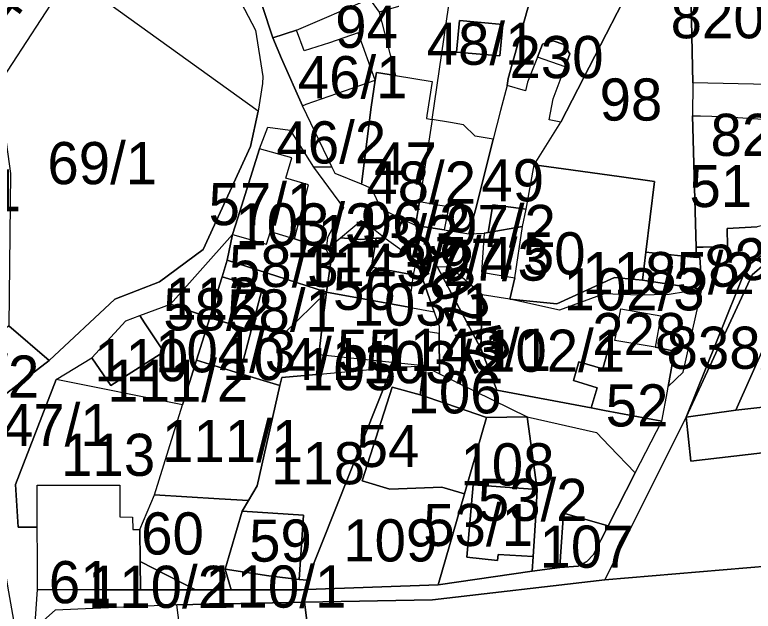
# Model space of a CAD drawing. Extents: x -623250 to -619626, y -1079612 to -1075424.
# Drawn here: x -621422.3 to -621247.2, y -1077337.8 to -1077196.3 of the extents above; entities that cross this region are included whole.
import ezdxf

# ---------------------------------------------------------------- set-up
doc = ezdxf.new("R2010")
doc.units = 0
doc.layers.add('Parcela nároku', color=7, linetype='Continuous')
doc.layers.add('Parcelní číslo', color=7, linetype='Continuous')

msp = doc.modelspace()

# ---------------------------------------------------------------- linework, layer by layer
at = {"layer": 'Parcela nároku'}
for points in [[(-621283.01, -1077121.21), (-621280.89, -1077123.84), (-621305.26, -1077211.45), (-621305.57, -1077213.07), (-621307.14, -1077219), (-621308.84, -1077225.83), (-621313.14, -1077225.09), (-621315.88, -1077222.42), (-621319, -1077221.89), (-621323.33, -1077221.15), (-621310.49, -1077133.23)], [(-621280.89, -1077123.84), (-621275.26, -1077129.83), (-621268.72, -1077174.87), (-621292.8, -1077221.78), (-621295.55, -1077221.25), (-621294.6, -1077216.21), (-621291.75, -1077208.69), (-621290.65, -1077205.56), (-621292.09, -1077203.39), (-621294.65, -1077202.49), (-621297.14, -1077203.31), (-621298.37, -1077206.39), (-621300.69, -1077212.33), (-621301.16, -1077214.33), (-621305.57, -1077213.07), (-621305.26, -1077211.45)], [(-621323.3, -1077212.12), (-621324.59, -1077220.22), (-621324.7, -1077220.92), (-621323.33, -1077221.15), (-621310.49, -1077133.23), (-621335.24, -1077144.05), (-621330.77, -1077177.42), (-621328.62, -1077193.52), (-621335.86, -1077195.7), (-621332.02, -1077210.68)], [(-621344.27, -1077183.78), (-621362.96, -1077165.79), (-621384.05, -1077157.04), (-621368.64, -1077178.95), (-621361.11, -1077201.81), (-621355.51, -1077199.95), (-621338.15, -1077192.45), (-621342.75, -1077185.94)], [(-621409.34, -1077186.93), (-621385.94, -1077160.33), (-621365.2, -1077199.94), (-621363.51, -1077210.97), (-621363.55, -1077212.6), (-621364.55, -1077219.18)], [(-621234.38, -1077170.7), (-621225.78, -1077225.43), (-621243.53, -1077212.83), (-621261.46, -1077212.45), (-621262.25, -1077175.25)], [(-621261.54, -1077220.29), (-621260.68, -1077251.44), (-621260.63, -1077253.88), (-621272.64, -1077252.66), (-621270.59, -1077235.87), (-621278.94, -1077234.7), (-621292.18, -1077232.85), (-621299.13, -1077231.88), (-621292.8, -1077221.78), (-621268.72, -1077174.87), (-621262.25, -1077175.25), (-621261.46, -1077212.45)], [(-621414.18, -1077278.35), (-621398.59, -1077263.79), (-621387.96, -1077259.7), (-621377.6, -1077252.01), (-621366.43, -1077227.54), (-621364.55, -1077219.18), (-621409.34, -1077186.93), (-621429.78, -1077218.32), (-621424.96, -1077221.94), (-621423.29, -1077233.96), (-621423.71, -1077270.11)], [(-621335.86, -1077195.7), (-621332.02, -1077210.68), (-621336.56, -1077210.03), (-621336.84, -1077211.83), (-621340.84, -1077200.6), (-621347.63, -1077202.95), (-621353.64, -1077204.86), (-621355.51, -1077199.95), (-621338.15, -1077192.45)], [(-621316.87, -1077197.68), (-621306.56, -1077198.59), (-621307.27, -1077206.06), (-621317.58, -1077205.15)], [(-621317.58, -1077205.15), (-621307.27, -1077206.06), (-621306.56, -1077198.59), (-621316.87, -1077197.68)], [(-621353.64, -1077204.86), (-621355.51, -1077199.95), (-621361.11, -1077201.81), (-621359.04, -1077206.69), (-621354.1, -1077217.94), (-621353.17, -1077217.54), (-621336.84, -1077211.83), (-621340.84, -1077200.6), (-621347.63, -1077202.95)], [(-621294.65, -1077202.49), (-621292.09, -1077203.39), (-621290.65, -1077205.56), (-621291.75, -1077208.69), (-621298.37, -1077206.39), (-621297.14, -1077203.31)], [(-621307.14, -1077219), (-621308.84, -1077225.83), (-621312.88, -1077242.04), (-621314.62, -1077248.24), (-621310.96, -1077248.15), (-621310.04, -1077247.99), (-621308.92, -1077241.39), (-621301.01, -1077242.43), (-621299.13, -1077231.88), (-621292.8, -1077221.78), (-621295.55, -1077221.25), (-621294.6, -1077216.21), (-621291.75, -1077208.69), (-621298.37, -1077206.39), (-621300.69, -1077212.33), (-621301.16, -1077214.33), (-621305.57, -1077213.07)], [(-621332.02, -1077210.68), (-621323.3, -1077212.12), (-621324.59, -1077220.22), (-621324.7, -1077220.92), (-621323.33, -1077221.15), (-621326.33, -1077240.57), (-621327.29, -1077246.34), (-621335.32, -1077242.42), (-621337.74, -1077237.5), (-621340.1, -1077236.53), (-621337.82, -1077218.19), (-621336.84, -1077211.83), (-621336.56, -1077210.03)], [(-621353.17, -1077217.54), (-621336.84, -1077211.83), (-621337.82, -1077218.19), (-621340.1, -1077236.53), (-621346.34, -1077233.96), (-621347.1, -1077232.4), (-621354.1, -1077217.94)], [(-621261.46, -1077212.45), (-621261.54, -1077220.29), (-621259.67, -1077220.32), (-621254.27, -1077220.41), (-621241.4, -1077221.33), (-621240.16, -1077230.42), (-621236.21, -1077229.88), (-621224.13, -1077237), (-621225.78, -1077225.43), (-621243.53, -1077212.83)], [(-621254.27, -1077220.41), (-621241.4, -1077221.33), (-621240.16, -1077230.42), (-621236.21, -1077229.88), (-621234.49, -1077242.48), (-621234.26, -1077244.2), (-621243.25, -1077245.92), (-621246.23, -1077246.61), (-621253.36, -1077246.98), (-621253.24, -1077251.28), (-621259.06, -1077251.41), (-621260.68, -1077251.44), (-621261.54, -1077220.29), (-621259.67, -1077220.32)], [(-621319.38, -1077241.83), (-621320.51, -1077247.34), (-621314.62, -1077248.24), (-621312.88, -1077242.04), (-621308.84, -1077225.83), (-621313.14, -1077225.09), (-621315.88, -1077222.42), (-621319, -1077221.89), (-621323.33, -1077221.15), (-621326.33, -1077240.57), (-621321.51, -1077241.51)], [(-621362.28, -1077222.94), (-621357, -1077223.71), (-621351.46, -1077232.43), (-621344.34, -1077242.13), (-621348.18, -1077249.16), (-621348.48, -1077252.01), (-621355.98, -1077249.43), (-621352.62, -1077236.67), (-621357.99, -1077235.06), (-621356.6, -1077230.27), (-621364.27, -1077228.08)], [(-621364.27, -1077228.08), (-621369.38, -1077244.49), (-621370.67, -1077248.45), (-621362.58, -1077250.74), (-621361.69, -1077247.69), (-621355.98, -1077249.43), (-621352.62, -1077236.67), (-621357.99, -1077235.06), (-621356.6, -1077230.27)], [(-621282.44, -1077290.17), (-621285.64, -1077289.56), (-621307.96, -1077285.34), (-621311.76, -1077275.51), (-621322.05, -1077256.19), (-621327.29, -1077246.34), (-621335.32, -1077242.42), (-621337.74, -1077237.5), (-621340.1, -1077236.53), (-621346.34, -1077233.96), (-621347.1, -1077232.4), (-621351.46, -1077232.43), (-621344.34, -1077242.13), (-621348.18, -1077249.16), (-621348.48, -1077252.01), (-621345.09, -1077249.2), (-621340.12, -1077245.09), (-621336.85, -1077247.39), (-621334.48, -1077249.33), (-621327.12, -1077254.63), (-621322.86, -1077266.78), (-621321.66, -1077270.19), (-621321.65, -1077271.91), (-621321.59, -1077281.47), (-621300.81, -1077291.72), (-621284.31, -1077295.45), (-621281.27, -1077298.62), (-621275.15, -1077305.01), (-621268.83, -1077292.74)], [(-621299.13, -1077231.88), (-621292.18, -1077232.85), (-621278.94, -1077234.7), (-621270.59, -1077235.87), (-621272.64, -1077252.66), (-621273.45, -1077259.28), (-621280.07, -1077258.66), (-621293.78, -1077264.9), (-621304.89, -1077263.8), (-621303.75, -1077258.75), (-621301.93, -1077246.55), (-621301.01, -1077242.43)], [(-621327.29, -1077246.34), (-621326.33, -1077240.57), (-621321.51, -1077241.51), (-621319.38, -1077241.83), (-621320.51, -1077247.34)], [(-621308.92, -1077241.39), (-621310.04, -1077247.99), (-621301.93, -1077246.55), (-621301.01, -1077242.43)], [(-621345.09, -1077249.2), (-621340.12, -1077245.09), (-621336.85, -1077247.39), (-621334.48, -1077249.33), (-621336.6, -1077249.29), (-621340.33, -1077249.63)], [(-621311.6, -1077257.38), (-621303.75, -1077258.75), (-621304.89, -1077263.8), (-621311.44, -1077262.76), (-621319.09, -1077256.09), (-621322.05, -1077256.19), (-621327.29, -1077246.34), (-621320.51, -1077247.34), (-621314.62, -1077248.24), (-621310.96, -1077248.15)], [(-621310.96, -1077248.15), (-621311.6, -1077257.38), (-621303.75, -1077258.75), (-621301.93, -1077246.55), (-621310.04, -1077247.99)], [(-621385.38, -1077264.96), (-621370.67, -1077248.45), (-621371.95, -1077254.49), (-621373.14, -1077258.45), (-621373.74, -1077260.43), (-621376.08, -1077268.19)], [(-621371.95, -1077254.49), (-621370.67, -1077248.45), (-621362.58, -1077250.74), (-621361.69, -1077247.69), (-621355.98, -1077249.43), (-621348.48, -1077252.01), (-621347.24, -1077254.38), (-621348.39, -1077262.15)], [(-621348.48, -1077252.01), (-621345.09, -1077249.2), (-621340.33, -1077249.63), (-621336.6, -1077249.29), (-621337.72, -1077256.19), (-621327.8, -1077257.99), (-621328.83, -1077265.7), (-621348.39, -1077262.15), (-621347.24, -1077254.38)], [(-621337.72, -1077256.19), (-621336.6, -1077249.29), (-621334.48, -1077249.33), (-621327.12, -1077254.63), (-621327.8, -1077257.99)], [(-621248.65, -1077256), (-621241.85, -1077250.96), (-621233.44, -1077250.14), (-621234.48, -1077252.35), (-621238.42, -1077252.8), (-621242.78, -1077254.01), (-621247.45, -1077257.99), (-621263.08, -1077291.76)], [(-621214.67, -1077268.16), (-621211.16, -1077267.99), (-621209.97, -1077285.55), (-621251.27, -1077290.14), (-621234.48, -1077252.35), (-621212.23, -1077250.58), (-621211.9, -1077255.8), (-621215.39, -1077255.93), (-621220.22, -1077256.12), (-621228.03, -1077256.42), (-621227.94, -1077259.11), (-621228.58, -1077259.16), (-621228.11, -1077268.82), (-621219.54, -1077268.4)], [(-621260.63, -1077253.88), (-621259.84, -1077253.85), (-621259.33, -1077261.42), (-621273.45, -1077259.28), (-621272.64, -1077252.66)], [(-621242.78, -1077254.01), (-621238.42, -1077252.8), (-621234.48, -1077252.35), (-621251.27, -1077290.14), (-621263.08, -1077291.76), (-621247.45, -1077257.99)], [(-621371.95, -1077254.49), (-621348.39, -1077262.15), (-621358.41, -1077271.96), (-621365.87, -1077269.81), (-621363.64, -1077261.33), (-621373.14, -1077258.45)], [(-621327.8, -1077257.99), (-621328.83, -1077265.7), (-621322.86, -1077266.78), (-621327.12, -1077254.63)], [(-621319.09, -1077256.09), (-621322.05, -1077256.19), (-621311.76, -1077275.51), (-621311.44, -1077262.76)], [(-621373.14, -1077258.45), (-621363.64, -1077261.33), (-621365.87, -1077269.81), (-621366.23, -1077271.2), (-621370.99, -1077269.68), (-621376.08, -1077268.19), (-621373.74, -1077260.43)], [(-621280.07, -1077258.66), (-621273.45, -1077259.28), (-621259.33, -1077261.42), (-621267.12, -1077262.69), (-621274.19, -1077262.86), (-621282.52, -1077262.55), (-621293.15, -1077266.4), (-621304.89, -1077263.8), (-621293.78, -1077264.9)], [(-621358.41, -1077271.96), (-621348.39, -1077262.15), (-621349.23, -1077268.87), (-621350.23, -1077276.95), (-621350.81, -1077281.62), (-621359.01, -1077282.36), (-621359.43, -1077284.23), (-621368.91, -1077281.38), (-621366.23, -1077271.2), (-621365.87, -1077269.81)], [(-621321.66, -1077270.19), (-621321.65, -1077271.91), (-621324.32, -1077271.55), (-621325.32, -1077279.63), (-621350.23, -1077276.95), (-621349.23, -1077268.87), (-621348.39, -1077262.15), (-621328.83, -1077265.7), (-621322.86, -1077266.78)], [(-621304.89, -1077263.8), (-621311.44, -1077262.76), (-621311.76, -1077275.51), (-621307.96, -1077285.34), (-621285.64, -1077289.56), (-621284.2, -1077284.82), (-621289.82, -1077283.11), (-621288.52, -1077278.62), (-621282.84, -1077280.34), (-621280.65, -1077272.23), (-621279.79, -1077272.48), (-621278.58, -1077266.08), (-621269.11, -1077267.75), (-621270.43, -1077275.2), (-621265.82, -1077276.13), (-621267.34, -1077284.52), (-621263.75, -1077281.07), (-621263.09, -1077277.96), (-621259.33, -1077261.42), (-621267.12, -1077262.69), (-621274.19, -1077262.86), (-621282.52, -1077262.55), (-621293.15, -1077266.4)], [(-621385.38, -1077264.96), (-621376.08, -1077268.19), (-621379.25, -1077278.28), (-621382.57, -1077288.87), (-621412.46, -1077282.86), (-621404.03, -1077277.68), (-621399.54, -1077284.23), (-621386.94, -1077276.31), (-621391.51, -1077269.39), (-621392.65, -1077267.66)], [(-621279.79, -1077272.48), (-621278.58, -1077266.08), (-621269.11, -1077267.75), (-621270.43, -1077275.2), (-621279.99, -1077273.57)], [(-621392.65, -1077267.66), (-621391.51, -1077269.39), (-621386.94, -1077276.31), (-621399.54, -1077284.23), (-621404.03, -1077277.68), (-621395.97, -1077268.89)], [(-621379.25, -1077278.28), (-621376.08, -1077268.19), (-621370.99, -1077269.68), (-621366.23, -1077271.2), (-621368.91, -1077281.38)], [(-621423.71, -1077270.11), (-621434.34, -1077279.24), (-621430.86, -1077291.13), (-621414.18, -1077278.35)], [(-621324.32, -1077271.55), (-621325.32, -1077279.63), (-621321.59, -1077281.47), (-621321.65, -1077271.91)], [(-621279.79, -1077272.48), (-621280.65, -1077272.23), (-621282.84, -1077280.34), (-621288.52, -1077278.62), (-621289.82, -1077283.11), (-621284.2, -1077284.82), (-621285.64, -1077289.56), (-621282.44, -1077290.17), (-621268.83, -1077292.74), (-621267.53, -1077285.57), (-621267.34, -1077284.52), (-621265.82, -1077276.13), (-621270.43, -1077275.2), (-621279.99, -1077273.57)], [(-621389.16, -1077310.24), (-621382.57, -1077288.87), (-621379.25, -1077278.28), (-621368.91, -1077281.38), (-621359.43, -1077284.23), (-621364.81, -1077308.05), (-621366.85, -1077311.52), (-621373.84, -1077311.12)], [(-621350.23, -1077276.95), (-621350.81, -1077281.62), (-621332.91, -1077280.01), (-621325.32, -1077279.63)], [(-621368.36, -1077314.11), (-621366.85, -1077311.52), (-621364.81, -1077308.05), (-621359.43, -1077284.23), (-621359.01, -1077282.36), (-621350.81, -1077281.62), (-621332.91, -1077280.01), (-621353, -1077330.46), (-621354.89, -1077330.27), (-621353.85, -1077314.99)], [(-621339.89, -1077306.92), (-621333.35, -1077308.83), (-621320.99, -1077308.39), (-621315.65, -1077309.94), (-621321.87, -1077331.52), (-621353.07, -1077332.66), (-621353, -1077330.46), (-621332.91, -1077280.01), (-621325.32, -1077279.63), (-621326.19, -1077286.46), (-621332.77, -1077284.63)], [(-621325.32, -1077279.63), (-621321.59, -1077281.47), (-621300.81, -1077291.72), (-621310.43, -1077291.86), (-621320.08, -1077288.55), (-621326.19, -1077286.46)], [(-621251.27, -1077290.14), (-621209.97, -1077285.55), (-621127.98, -1077280.25), (-621128.64, -1077289.04), (-621208.91, -1077296.04), (-621261.94, -1077302.25), (-621263.08, -1077291.76)], [(-621416.98, -1077315.22), (-621417.01, -1077307.9), (-621399.23, -1077307.9), (-621397.39, -1077307.94), (-621397.36, -1077315.45), (-621394.4, -1077315.49), (-621394.34, -1077318.42), (-621392.68, -1077318.44), (-621389.16, -1077310.24), (-621382.57, -1077288.87), (-621412.46, -1077282.86), (-621422.17, -1077307.77), (-621421.49, -1077317.9), (-621416.97, -1077317.91)], [(-621339.89, -1077306.92), (-621332.77, -1077284.63), (-621326.19, -1077286.46), (-621320.08, -1077288.55), (-621310.43, -1077291.86), (-621312.64, -1077299.51), (-621315.65, -1077309.94), (-621320.99, -1077308.39), (-621333.35, -1077308.83)], [(-621261.94, -1077302.25), (-621208.91, -1077296.04), (-621128.64, -1077289.04), (-621130.79, -1077317.53), (-621282.39, -1077330.34), (-621263.08, -1077291.76)], [(-621310.43, -1077291.86), (-621300.81, -1077291.72), (-621298.39, -1077308.94), (-621313.61, -1077307.84), (-621315.08, -1077325.03), (-621307.83, -1077325.76), (-621307.68, -1077324.34), (-621299.37, -1077324.81), (-621299.58, -1077328.28), (-621321.87, -1077331.52), (-621315.65, -1077309.94), (-621312.64, -1077299.51)], [(-621300.81, -1077291.72), (-621284.31, -1077295.45), (-621281.27, -1077298.62), (-621275.15, -1077305.01), (-621281.58, -1077317.52), (-621292.15, -1077314.57), (-621292.92, -1077324.84), (-621293.05, -1077327.44), (-621299.58, -1077328.28), (-621299.37, -1077324.81), (-621298.77, -1077315.04), (-621298.39, -1077308.94)], [(-621397.36, -1077315.45), (-621394.4, -1077315.49), (-621394.34, -1077318.42), (-621392.68, -1077318.44), (-621392.6, -1077326.01), (-621392.53, -1077332.73), (-621401.09, -1077332.72), (-621416.91, -1077332.7), (-621416.94, -1077325.32), (-621416.97, -1077317.91), (-621416.98, -1077315.22), (-621417.01, -1077307.9), (-621399.23, -1077307.9), (-621397.39, -1077307.94)], [(-621313.61, -1077307.84), (-621298.39, -1077308.94), (-621298.77, -1077315.04), (-621299.37, -1077324.81), (-621307.68, -1077324.34), (-621307.83, -1077325.76), (-621315.08, -1077325.03)], [(-621372.45, -1077327.85), (-621371, -1077332.72), (-621378.53, -1077332.72), (-621379.48, -1077332.72), (-621392.6, -1077326.01), (-621392.68, -1077318.44), (-621389.16, -1077310.24), (-621373.84, -1077311.12), (-621366.85, -1077311.52), (-621368.36, -1077314.11)], [(-621372.45, -1077327.85), (-621368.36, -1077314.11), (-621353.85, -1077314.99), (-621354.89, -1077330.27), (-621362.06, -1077329.39)], [(-621293.05, -1077327.44), (-621292.92, -1077324.84), (-621292.15, -1077314.57), (-621281.58, -1077317.52), (-621285.09, -1077324.36), (-621286.6, -1077326.04), (-621288.73, -1077327.09)], [(-621323.27, -1077335.09), (-621282.39, -1077330.34), (-621130.79, -1077317.53), (-621132.51, -1077357.74), (-621240.85, -1077364.46), (-621349.12, -1077371.13), (-621353.6, -1077335.7)], [(-621392.6, -1077326.01), (-621379.48, -1077332.72), (-621392.53, -1077332.73)], [(-621372.45, -1077327.85), (-621362.06, -1077329.39), (-621354.89, -1077330.27), (-621353, -1077330.46), (-621353.07, -1077332.66), (-621354.34, -1077332.71), (-621371, -1077332.72)], [(-621383.87, -1077336.3), (-621353.6, -1077335.7), (-621349.12, -1077371.13), (-621379.17, -1077372.99)], [(-621379.17, -1077372.99), (-621383.87, -1077336.3), (-621412.76, -1077337.56), (-621417.57, -1077341.86), (-621418.32, -1077354.2), (-621414.45, -1077355.34), (-621414.57, -1077350.94), (-621414.74, -1077344.54), (-621399.69, -1077344.22), (-621399.53, -1077350.53), (-621399.5, -1077351.73), (-621390.49, -1077351.5), (-621390.14, -1077367.74), (-621399.09, -1077368.05), (-621411.39, -1077368.36), (-621414.09, -1077368.43), (-621414.24, -1077362.93), (-621414.33, -1077359.83), (-621418.69, -1077360.17), (-621420.08, -1077382.44), (-621380.43, -1077384.11)]]:
    msp.add_lwpolyline(points, close=True, dxfattribs=at)
for points in [[(-621385.94, -1077160.33), (-621365.2, -1077199.94), (-621363.51, -1077210.97), (-621363.55, -1077212.6), (-621364.55, -1077219.18), (-621366.43, -1077227.54), (-621377.6, -1077252.01), (-621387.96, -1077259.7), (-621398.59, -1077263.79), (-621414.18, -1077278.35), (-621430.86, -1077291.13), (-621432.17, -1077292.28), (-621427.72, -1077298.01), (-621426.4, -1077312.7), (-621426.21, -1077319.12), (-621424.02, -1077331.91), (-621422.64, -1077339.94)], [(-621417.57, -1077341.86), (-621416.91, -1077332.7), (-621416.94, -1077325.32), (-621416.97, -1077317.91), (-621421.49, -1077317.9), (-621422.17, -1077307.77), (-621412.46, -1077282.86), (-621404.03, -1077277.68), (-621395.97, -1077268.89), (-621392.65, -1077267.66), (-621385.38, -1077264.96), (-621370.67, -1077248.45), (-621369.38, -1077244.49), (-621364.27, -1077228.08), (-621362.28, -1077222.94), (-621357, -1077223.71), (-621351.46, -1077232.43), (-621347.1, -1077232.4), (-621354.1, -1077217.94), (-621359.04, -1077206.69), (-621361.11, -1077201.81), (-621368.64, -1077178.95)], [(-621409.34, -1077186.93), (-621429.78, -1077218.32), (-621438.97, -1077232.01), (-621449.93, -1077257.56), (-621455.88, -1077265.89), (-621464.93, -1077283.24), (-621467.77, -1077288.67), (-621474.34, -1077300.26), (-621482.14, -1077312.1), (-621489.64, -1077319.57), (-621495.56, -1077325.19), (-621510.49, -1077339.36)], [(-621241.85, -1077250.96), (-621248.65, -1077256), (-621263.08, -1077291.76), (-621282.39, -1077330.34), (-621323.27, -1077335.09), (-621353.6, -1077335.7), (-621383.87, -1077336.3), (-621412.76, -1077337.56), (-621417.57, -1077341.86), (-621416.91, -1077332.7), (-621401.09, -1077332.72), (-621392.53, -1077332.73), (-621379.48, -1077332.72), (-621378.53, -1077332.72), (-621371, -1077332.72), (-621354.34, -1077332.71), (-621353.07, -1077332.66), (-621321.87, -1077331.52), (-621299.58, -1077328.28), (-621293.05, -1077327.44), (-621288.73, -1077327.09), (-621286.6, -1077326.04), (-621285.09, -1077324.36), (-621281.58, -1077317.52), (-621275.15, -1077305.01), (-621268.83, -1077292.74), (-621267.53, -1077285.57), (-621267.34, -1077284.52), (-621263.75, -1077281.07), (-621263.09, -1077277.96), (-621259.33, -1077261.42), (-621259.84, -1077253.85), (-621260.63, -1077253.88), (-621260.68, -1077251.44), (-621259.06, -1077251.41), (-621253.24, -1077251.28), (-621253.36, -1077246.98), (-621246.23, -1077246.61)]]:
    msp.add_lwpolyline(points, dxfattribs=at)

# ---------------------------------------------------------------- texts
at = {"layer": 'Parcelní číslo'}
for s, rotation, p in [('1184/8', 54.0048, (-621436.96, -1077217.95)), ('837/3', 12.0929, (-621257.17, -1077261.51)), ('102/2', 296.6225, (-621327.92, -1077252.24))]:
    msp.add_text(s, height=10, rotation=rotation, dxfattribs=at).set_placement(p)
for s, p in [('820/8', (-621266.76, -1077201.88)), ('94', (-621346.32, -1077204.16)), ('48/1', (-621324.61, -1077208.17)), ('230', (-621304.98, -1077211.34)), ('46/1', (-621355.19, -1077216.11)), ('98', (-621283.61, -1077221.41)), ('820/3', (-621257.29, -1077229.79)), ('46/2', (-621360.25, -1077231.59)), ('69/1', (-621414.58, -1077236.5)), ('47', (-621337.07, -1077236.58)), ('48/2', (-621338.94, -1077241.11)), ('49', (-621311.65, -1077240.57)), ('54/1', (-621446.81, -1077242.95)), ('51', (-621262.3, -1077241.93)), ('57/1', (-621376.34, -1077246.23)), ('103/3', (-621369.99, -1077251.04)), ('96/2', (-621340.27, -1077250.71)), ('97/2', (-621320.01, -1077251.41)), ('1143/3', (-621357.96, -1077253.83)), ('97/4', (-621330.19, -1077259.01)), ('50', (-621301.81, -1077257.91)), ('58/3', (-621371.52, -1077260.89)), ('1143/2', (-621354.16, -1077260.62)), ('97/3', (-621321.66, -1077259.39)), ('1185/2', (-621287.7, -1077262.59)), ('56', (-621346.84, -1077266.33)), ('102/3', (-621292.16, -1077266.44)), ('112', (-621386.57, -1077268.64)), ('58/2', (-621387.11, -1077271.19)), ('103/1', (-621342.2, -1077270.06)), ('58/1', (-621371.95, -1077271.46)), ('228', (-621285.35, -1077277.06)), ('104/3', (-621389.03, -1077281.13)), ('55', (-621345.92, -1077280.99)), ('1143/1', (-621336.03, -1077280.81)), ('102/1', (-621311.02, -1077281.01)), ('838/3', (-621267.73, -1077280.3)), ('110', (-621403.46, -1077283.24)), ('104/1', (-621373.14, -1077282.98)), ('103/2', (-621339.85, -1077283.72)), ('69/2', (-621442.52, -1077287.15)), ('105', (-621354.15, -1077285.38)), ('111/2', (-621400.39, -1077288.11)), ('106', (-621329.16, -1077290.87)), ('52', (-621282.17, -1077293.98)), ('1147/1', (-621440.23, -1077298.64)), ('111/1', (-621387.38, -1077302.42)), ('54', (-621341.23, -1077303.6)), ('113', (-621411.31, -1077305.71)), ('118', (-621361.53, -1077307.7)), ('108', (-621316.62, -1077307.97)), ('53/2', (-621312.48, -1077316.39)), ('53/1', (-621325.44, -1077322.34)), ('60', (-621392.34, -1077324.37)), ('59', (-621366.74, -1077326.06)), ('109', (-621344.41, -1077326.01)), ('107', (-621297.85, -1077327.5)), ('61', (-621414.24, -1077335.92)), ('110/2', (-621404.96, -1077337.03)), ('110/1', (-621377.15, -1077336.96))]:
    msp.add_text(s, height=10, dxfattribs=at).set_placement(p)

doc.saveas('drawing.dxf')
